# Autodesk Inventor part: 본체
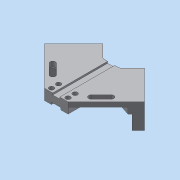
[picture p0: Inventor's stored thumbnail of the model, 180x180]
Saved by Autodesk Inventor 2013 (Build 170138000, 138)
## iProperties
Created: 2019-04
Part Number: 본체
Material: 알루미늄 6061
Document SubType Name: Modeling
Designer: dgall
Density: 2.71 g/cm^3
Mass: 603.737 g
Surface Area: 426.536 cm^2
Volume: 222.781 cm^3
Author: dgall
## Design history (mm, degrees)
sketch "스케치1"
  geometry: L1 (0, 84.853)-(0, -84.853); L2 (-84.853, 0)-(-35.355, 49.497); L3 (0, 84.853)-(-35.355, 49.497); L4 (84.853, 0)-(35.355, 49.497); L5 (35.355, 49.497)-(0, 84.853); L6 (-20, -64.853)-(20, -64.853); L7 (84.853, 0)-(20, -64.853); L8 (-20, -64.853)-(-84.853, 0); L9 (0, -84.853)-(-20, -64.853); L10 (0, -84.853)-(20, -64.853); L11 (-35.355, 49.497)-(-14.005, 28.147); L12 (-14.005, 28.147)-(14.005, 28.147); L13 (14.005, 28.147)-(35.355, 49.497); L14 (-74.246, -10.607)-(-24.749, 38.891); L15 (24.749, 38.891)-(74.246, -10.607); L16 (-70.711, -14.142)-(-49.497, -7.071); L17 (-49.497, -7.071)-(-20, -36.569); L18 (-20, -36.569)-(-20, -64.853); L19 (70.711, -14.142)-(49.497, -7.071); L20 (49.497, -7.071)-(20, -36.569); L21 (20, -36.569)-(20, -64.853); L22 (-52.679, -24.395)-(-35.709, -41.366); L23 (-46.315, -18.031)-(-29.345, -35.002); L24 (46.315, -18.031)-(29.345, -35.002); L25 (35.709, -41.366)-(52.679, -24.395); L26 (-8, 28.147)-(-8, -64.853); L27 (8, 28.147)-(8, -64.853); A1 r 4.5 centre (-49.497, -21.213) between (-46.315, -18.031) and (-52.679, -24.395); A2 r 4.5 centre (-32.527, -38.184) between (-35.709, -41.366) and (-29.345, -35.002); A3 r 4.5 centre (49.497, -21.213) between (52.679, -24.395) and (46.315, -18.031); A4 r 4.5 centre (32.527, -38.184) between (29.345, -35.002) and (35.709, -41.366); 2 further points
  constraints: 56 end point, 13 perpendicular, 10 point on line, 8 point on circle, 5 parallel, 4 centre point, 4 tangent, 3 collinear, 3 equal radius, 2 vertical, 1 coincident, 1 midpoint
  dimensions: "d0" = 120 distance of L4.start L1.start; "d3" = 70 distance of L2.start L2.end; "d4" = 70 distance of L4.start L4.end; "d5" = 40 distance of L6.start L6.end; "d6" = 93 distance between parallel lines of L6 L12; "d7" = 15 distance between parallel lines of L2 L14; "d8" = 15 distance between parallel lines of L4 L15; "d9" = 20 distance of L2.start L16.start; "d10" = 20 distance between parallel lines of L8 L17; "d11" = 30 distance from line of L2 L16.end; "d12" = 20 distance between parallel lines of L7 L20; "d13" = 20 distance of L4.start L19.start; "d14" = 30 distance from line of L19.end L4; "d15" = 9 diameter of A1; "d16" = 24 distance of A2.centre A1.centre; "d17" = 40 distance from line of L2 A1.centre; "d18" = 10 distance from line of L8 A1.centre; "d19" = 10 distance from line of L8 A2.centre; "d20" = 24 distance of A4.centre A3.centre; "d21" = 40 distance from line of L4 A3.centre; "d22" = 10 distance from line of L7 A3.centre; "d23" = 10 distance from line of L7 A4.centre; "d24" = 16 distance between parallel lines of L27 L26; "d25" = 8 distance between parallel lines of L26 L1
extrude "돌출1" new body sketch "스케치1" distance "d26" = 8; taper "d27" = 0 deg
extrude "돌출2" join sketch "스케치1" distance "d28" = 18; taper "d29" = 0 deg
extrude "돌출3" join sketch "스케치1" distance "d30" = 42; taper "d31" = 0 deg
extrude "돌출4" join sketch "스케치1" distance "d32" = 18; taper "d33" = 0 deg
sketch "스케치2"
  geometry: L1 (-20, -64.853)-(20, -64.853) reference; L2 (14.005, 28.147)-(-14.005, 28.147) reference; L3 (-6, 28.147)-(-6, -64.853); L4 (6, 28.147)-(6, -64.853); 1 further point
  constraints: 4 end point, 4 point on line, 2 perpendicular
  dimensions: "d34" = 12 distance between parallel lines of L4 L3; "d35" = 6 distance from line of L3 point (0, 0)
extrude "돌출5" cut sketch "스케치2" distance "d36" = 3; taper "d37" = 0 deg
sketch "스케치3"
  geometry: L1 (-20, -64.853)-(20, -64.853) reference; L2 (14.005, 28.147)-(-14.005, 28.147) reference; L3 (-8, 28.147)-(-8, -64.853); L4 (8, 28.147)-(8, -64.853); 1 further point
  constraints: 4 end point, 4 point on line, 2 perpendicular
  dimensions: "d38" = 16 distance between parallel lines of L4 L3; "d39" = 8 distance from line of L3 point (0, 0)
extrude "돌출6" cut sketch "스케치3" distance "d40" = 3.5; taper "d41" = 0 deg
sketch "스케치5"
  geometry: L1 (6, 28.147)-(6, -64.853) reference; L2 (6, -64.853)-(20, -64.853) reference; L3 (6, -64.853)-(-6, -64.853) reference; L4 (0, -64.853)-(0, 0); L5 (-35.709, -41.366)-(-52.679, -24.395) reference; L6 (-46.315, -18.031)-(-29.345, -35.002) reference; L7 (-6, -64.853)-(-6, 28.147) reference; L8 (-6, 28.147)-(-14.005, 28.147) reference; L9 (-14.005, 28.147)-(-35.355, 49.497) reference; L10 (-35.355, 49.497)-(-84.853, 0) reference; L11 (-84.853, 0)-(-20, -64.853) reference; L12 (-20, -64.853)-(-6, -64.853) reference; A1 r 4.5 centre (-49.497, -21.213) between (-46.315, -18.031) and (-52.679, -24.395) reference; A2 r 4.5 centre (-32.527, -38.184) between (-35.709, -41.366) and (-29.345, -35.002) reference; 4 further points
  constraints: 2 end point, 2 horizontal alignment, 2 vertical alignment, 1 midpoint, 1 parallel
  dimensions: "d47" = 12 distance of point (14, -46.853) point (14, -58.853); "d49" = 6 distance from line of L2 point (14, -58.853); "d50" = 28 distance of point (-14, -58.853) point (14, -58.853); "d51" = 14 distance from line of point (14, -58.853) L4
hole "구멍1" sketch "스케치5" at (-14, -46.853), (14, -46.853), (14, -58.853), (-14, -58.853) diameter "d52" = 4.5; stored, may be unused: countersink angle "d56" = 90 deg, drill point angle "d58" = 118 deg; dims "d53" = 6, "d54" = 8, "d55" = 10, "d57" = 8
fillet "모깎기1" dims "d59" = 5
fillet "모깎기2" dims "d60" = 5
sketch "스케치7"
  geometry: L1 (-74.246, -10.607)-(-24.749, 38.891) reference; L2 (-24.749, 38.891)-(-35.355, 49.497) reference; 2 further points
  constraints: 1 other
  dimensions: "d63" = 35 distance from line of L2 point (-54.801, 19.445); "d64" = 7.5 distance from line of L1 point (-54.801, 19.445)
feature "엠보싱1" sketch "스케치7" dims "d65" = 0.5, "d66" = 0
node "솔리드1"
node "투영된 루프1"
